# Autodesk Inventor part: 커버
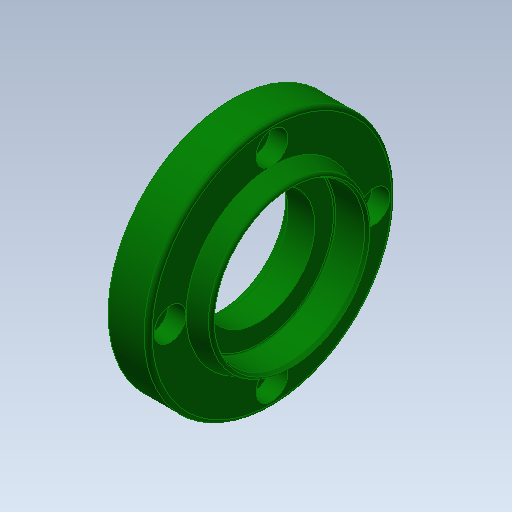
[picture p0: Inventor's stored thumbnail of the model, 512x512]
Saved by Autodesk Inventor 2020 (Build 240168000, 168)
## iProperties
Created: 2018-11
Part Number: 커버
Material: 알루미늄 6061
Document SubType Name: Modeling
Designer: mduedu
Density: 1 g/cm^3
Appearance: 진녹색
Author: mduedu
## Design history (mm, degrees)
revolve "회전1" stored, may be unused: angle "d7" = 90 deg
sketch "스케치2"
  geometry: L1 (0, -20)-(0, 20) reference; L2 (0, 20)-(3, 20) reference; L3 (3, 20)-(3, 31) reference; L4 (3, 31)-(13, 31) reference; L5 (13, 31)-(13, 21.5) reference; L6 (18, 20)-(18, -20) reference; L7 (13, -21.5)-(13, -31) reference; L8 (13, -31)-(3, -31) reference; L9 (3, -31)-(3, -20) reference; L10 (3, -20)-(0, -20) reference; L11 (0, 0)-(3, 0); L12 (3, 0)-(3, 16.5); L13 (3, 16.5)-(0, 16.5); L14 (0, 16.5)-(0, 0); L15 (3, 0)-(9.7, 0); L16 (9.7, 0)-(9.7, 14); L17 (9.7, 14)-(3, 14); L18 (3, 14)-(3, 0); L19 (9.7, 0)-(18, 0); L20 (18, 0)-(18, 19); L21 (18, 19)-(9.7, 19); L22 (9.7, 19)-(9.7, 0); L23 (13, 21.5)-(18, 20) reference; L24 (18, -20)-(13, -21.5) reference
  constraints: 24 end point, 6 parallel, 3 horizontal, 3 perpendicular, 1 point on line
  dimensions: "d8" = 38 diameter of L21 L19; "d10" = 28 diameter of L17 L15; "d11" = 33 diameter of L13 L11; "d12" = 3 distance of L12.end L13.end; "d13" = 8.3 distance of L20.end L21.end
revolve "회전2" sketch "스케치2" stored, may be unused: angle "d14" = 90 deg
fillet "모깎기1" dims "d15" = 0.3
chamfer "모따기1" distance "d16" = 0.8; stored, may be unused: second distance "d17" = 2, angle "d18" = 30 deg
fillet "모깎기2" dims "d19" = 1
chamfer "모따기2" distance "d20" = 0.5; stored, may be unused: second distance "d21" = 2, angle "d22" = 30 deg
sketch "스케치3" dims "d23" = 52
  geometry: 6 further points
  constraints: 2 vertical alignment, 1 coincident, 7 other
  dimensions: "d26" = 360 deg dimension on point (0, 0) point (0, 26) (derived)
sketch "스케치4"
  geometry: C1 r 1.621 at (0, 25.5) reference; C2 r 1.621 at (25.5, 0) reference; C3 r 1.621 at (0, -25.5) reference; C4 r 1.621 at (-25.5, 0) reference
hole "구멍2" sketch "스케치4" at (0, 25.5), (25.5, 0), (0, -25.5), (-25.5, 0) diameter "d38" = 4.5; stored, may be unused: countersink angle "d42" = 90 deg, drill point angle "d44" = 118 deg; dims "d39" = 8, "d40" = 8, "d41" = 4.4, "d43" = 10
node "솔리드1"
sketch "스케치1"
  geometry: L1 (0, 0)-(3, 0); L2 (3, 0)-(3, 20); L3 (3, 20)-(0, 20); L4 (0, 20)-(0, 0); L5 (3, 0)-(13, 0); L6 (13, 0)-(13, 31); L7 (13, 31)-(3, 31); L8 (3, 31)-(3, 0); L9 (13, 0)-(18, 0); L10 (18, 0)-(18, 20); L11 (13, 15)-(13, 0); L12 (18, 20)-(13, 21.5)
  constraints: 24 end point, 5 parallel, 3 horizontal, 3 perpendicular, 1 point on line
  dimensions: "d0" = 62 diameter of L7 L5; "d3" = 40 diameter of L3 L1; "d4" = 3 distance of L2.end L3.end; "d5" = 10 distance of L6.end L7.end; "d6" = 18 distance between parallel lines of L10 L4; "d35" = 40 diameter of L10.end L9; "d37" = 43 diameter of L12.end L9
node "참조1"
node "참조2"
node "참조3"
node "참조4"
node "절단 모서리 투영1"
